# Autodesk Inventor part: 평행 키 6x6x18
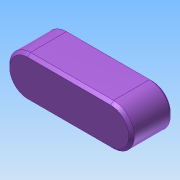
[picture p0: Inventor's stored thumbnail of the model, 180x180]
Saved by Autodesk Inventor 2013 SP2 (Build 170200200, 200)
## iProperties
Created: 2025-08
Part Number: 평행 키 6x6x18
Material: Generic
Document SubType Name: Modeling
Designer: i
Density: 1 g/cm^3
Author: i
변환 표준: STEP AP214IS
전처리기: Build: 200, Release: 2013 SP2 Update 6 - Date: Thu 07/17/2014
전송 단위: 밀리미터
불확실성: 0.01
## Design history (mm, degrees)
node "평행 키 6x6x181"
body "Solid1"
node "기준1"
